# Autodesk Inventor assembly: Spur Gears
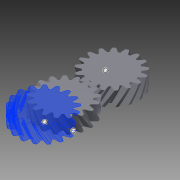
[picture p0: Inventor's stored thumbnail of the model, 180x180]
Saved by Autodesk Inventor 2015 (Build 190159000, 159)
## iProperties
Created: 2014-06
Part Number: Spur Gears
Document SubType Name: Assembly
Designer: User
Categories: <?xml version="1.0" encoding="UTF-16"?> <MemberInstance><Categories><FamilyTemplate/><ParamToTemplateMap><ParamToTemplate><ParamToTemplate CategoryParameter="//
ClientObjectVersion: 1
Author: User
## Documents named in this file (3)
- Z:\CAD Files\Belt_Extruder\Rev. C\Helical_Gear_Assembly\Design Accelerator\Spur Gears1.iam
- Z:\CAD Files\Belt_Extruder\Rev. C\Helical_Gear_Assembly\Design Accelerator\Spur Gear11.ipt
- Z:\CAD Files\Belt_Extruder\Rev. C\Helical_Gear_Assembly\Design Accelerator\Spur Gear21.ipt
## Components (2 placed, 2 different names)
1. Spur Gear1:1 — Rotation:1
2. Spur Gear2:1 — Rotation:1
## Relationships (1: RelateRotation 1)
- Rotation:1 [RelateRotation]: Spur Gear1:1 ↔ Spur Gear2:1
